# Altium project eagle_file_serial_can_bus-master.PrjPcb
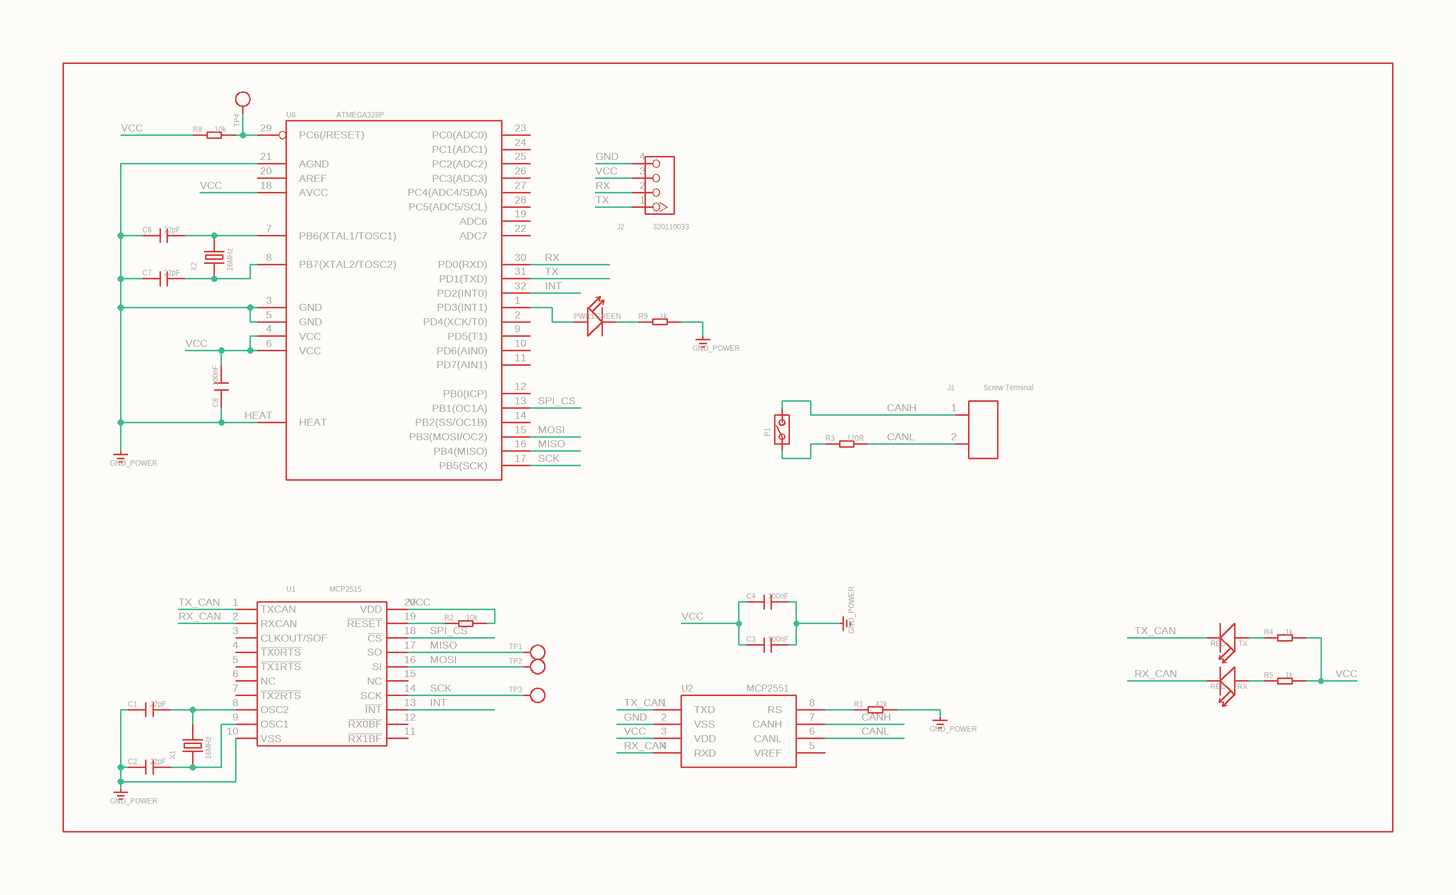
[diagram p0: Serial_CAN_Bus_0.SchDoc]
2 sheets, 34 parts. Net scope: global (net labels, ports and power ports of the same name join across sheets).
Board file: Serial_CAN_Bus.PcbDoc
Sheets:
  Serial_CAN_Bus_0.SchDoc
  Serial_CAN_Bus_1.SchDoc

## Sheet Serial_CAN_Bus_0.SchDoc: STM1120
size 255 x 156 mm; DESCRIPTION: microOBD 200 OBD-II Module; HW_REV: 1.4; PCB_REV: C; PCB_SPEC1: Layer Count: 4; PCB_SPEC2: Size: 1.3" x 0.59"; PCB_SPEC3: Finish Thickness: 0.049" - 0.052"; PCB_SPEC4: Copper Weight: 1oz; Origin: Eagle

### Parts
C1  22pF  [0603]
C2  22pF  [0603]
C3  100nF  [0603]
C4  100nF  [0603]
C6  22pF  [0603]
C7  22pF  [0603]
C8  100nF  [0603]
GND  GND_POWER
J1  Screw Terminal  [2P-3.5]
J2  320110033  [HW4-2.0]
P1  PAD-JUMPER-2P  [2P-SMD-1.78X1.27]  (value not drawn)
PWR1  GREEN  [LED-0603]
R1  47k  [0603]
R2  10k  [0603]
R3  120R  [0603]
R4  1k  [0603]
R5  1k  [0603]
R8  10k  [0603]
R9  1k  [0603]
RX  RED  [LED-0603]
TP1  PAD-TEST-POINT'4545'  [TP_4545]  (value not drawn)
TP2  PAD-TEST-POINT'4545'  [TP_4545]  (value not drawn)
TP3  PAD-TEST-POINT'4545'  [TP_4545]  (value not drawn)
TP4  PAD-TEST-POINT'4545'  [TP_4545]  (value not drawn)
TX  RED  [LED-0603]
U1  MCP2515  [TSSOP20-0.65-6.5X4.4MM]
U2  MCP2551  [SOIC8-6.0]
U6  ATMEGA328P  [MLF32X]
U$1  GND_POWER
U$2  GND_POWER
U$3  GND_POWER
U$4  GND_POWER
X1  16MHz  [X2-SMD-5.0X3.2X1.3MM]
X2  16MHz  [X2-SMD-5.0X3.2X1.3MM]

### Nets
CANH: J1.1 P1.2 U2.7(CANH)
CANL: J1.2 R3.2 U2.6(CANL)
GND: J2.4 U2.2(VSS)
INT: U1.13(~{INT}) U6.32(PD2(INT0))
MISO: TP1.T U1.17(SO) U6.16(PB4(MISO))
MOSI: TP2.T U1.16(SI) U6.15(PB3(MOSI/OC2))
RX: J2.2 U6.30(PD0(RXD))
RX_CAN: RX.- U1.2(RXCAN) U2.4(RXD)
SCK: TP3.T U1.14(SCK) U6.17(PB5(SCK))
SPI_CS: U1.18(~{CS}) U6.13(PB1(OC1A))
TX: J2.1 U6.31(PD1(TXD))
TX_CAN: TX.- U1.1(TXCAN) U2.1(TXD)
VCC: C3.1 C4.1 C8.2 J2.3 R2.2 R4.2 R5.2 R8.1 U1.20(VDD) U2.3(VDD) U6.4(VCC) U6.6(VCC) U6.18(AVCC)
NetC1_1: C1.1 C2.1 U1.10(VSS) U$2.?1(GND)
NetC1_2: C1.2 U1.8(OSC2) X1.2
NetC2_2: C2.2 U1.9(OSC1) X1.1
NetC3_2: C3.2 C4.2 U$3.?1(GND)
NetC6_1: C6.1 C7.1 C8.1 U6.3(GND) U6.5(GND) U6.21(AGND) U6.HEAT U$4.?1(GND)
NetC6_2: C6.2 U6.7(PB6(XTAL1/TOSC1)) X2.2
NetC7_2: C7.2 U6.8(PB7(XTAL2/TOSC2)) X2.1
NetGND_?1: GND.?1(GND) R1.2
NetP1_1: P1.1 R3.1
NetPWR1_+: PWR1.+ U6.1(PD3(INT1))
NetPWR1_-: PWR1.- R9.1
NetR1_1: R1.1 U2.8(RS)
NetR2_1: R2.1 U1.19(~{RESET})
NetR4_1: R4.1 TX.+
NetR5_1: R5.1 RX.+
NetR8_2: R8.2 TP4.T U6.29(PC6(/RESET))
NetR9_2: R9.2 U$1.?1(GND)

Not connected (* = marked no-connect by the designer): U1 3(CLKOUT/SOF) 4(~{TX0RTS}) 5(~{TX1RTS}) 6(NC) 7(~{TX2RTS}) 11(~{RX1BF}) 12(~{RX0BF}) 15(NC); U2 5(VREF); U6 2(PD4(XCK/T0)) 9(PD5(T1)) 10(PD6(AIN0)) 11(PD7(AIN1)) 12(PB0(ICP)) 14(PB2(SS/OC1B)) 19(ADC6) 20(AREF) 22(ADC7) 23(PC0(ADC0)) 24(PC1(ADC1)) 25(PC2(ADC2)) 26(PC3(ADC3)) 27(PC4(ADC4/SDA)) 28(PC5(ADC5/SCL))

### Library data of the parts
C1-C4 C6-C8 = C*-0603: Ceramic Capacitors; GateName_1: C; DeviceName: -0603; DeviceSetName: C*
GND U$1-U$4 = GND_POWER: GateName_1: G$1
J1 = SCREW-TERMINAL-2P'3.5': 2P-3.5:320110028;2P-5.0:320110031; GateName_1: G$1; DeviceName: '3.5'
J2 = GROVE-CONNECTOR-DIP-2.0: 4P-2.0:320110033;4P-2.0-90D:320110034; GateName_1: G$1; DeviceName: -2.0
P1 = PAD-JUMPER-2P: GateName_1: G$1; SymbolName_1: JP_SW-1
PWR1 RX TX = LED*'0603': GateName_1: LED; DeviceName: '0603'; DeviceSetName: LED*
R1-R5 R8 R9 = R*-0603: GateName_1: R; DeviceName: -0603; DeviceSetName: R*
TP1-TP4 = PAD-TEST-POINT'4545': PARTNO: DNP; GateName_1: TP; SymbolName_1: TEST_POINT; DeviceName: '4545'
U1 = MCP2515'ST': GateName_1: G$1; DeviceName: 'ST'
U2 = MCP2551-SOIC8: High-Speed CAN Transceiver   http://ww1.microchip.com/downloads/en/devicedoc/21667f.pdf; GateName_1: G$1; DeviceName: -SOIC8
U6 = MEGA8: GateName_1: G$1
X1 X2 = CRYSTAL-2P'5032': GateName_1: X; DeviceName: '5032'

## Sheet Serial_CAN_Bus_1.SchDoc: STM1120
size 20 x 20 mm; DESCRIPTION: microOBD 200 OBD-II Module; HW_REV: 1.4; PCB_REV: C; PCB_SPEC1: Layer Count: 4; PCB_SPEC2: Size: 1.3" x 0.59"; PCB_SPEC3: Finish Thickness: 0.049" - 0.052"; PCB_SPEC4: Copper Weight: 1oz; Origin: Eagle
